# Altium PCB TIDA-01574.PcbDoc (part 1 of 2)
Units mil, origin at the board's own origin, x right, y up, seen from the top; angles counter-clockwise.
Board outline 4950 x 3450 mil, 2 copper layers (Top Layer, Bottom Layer), stack 62 mil thick; 82 components, 33 nets, 179 pads, 119 vias.
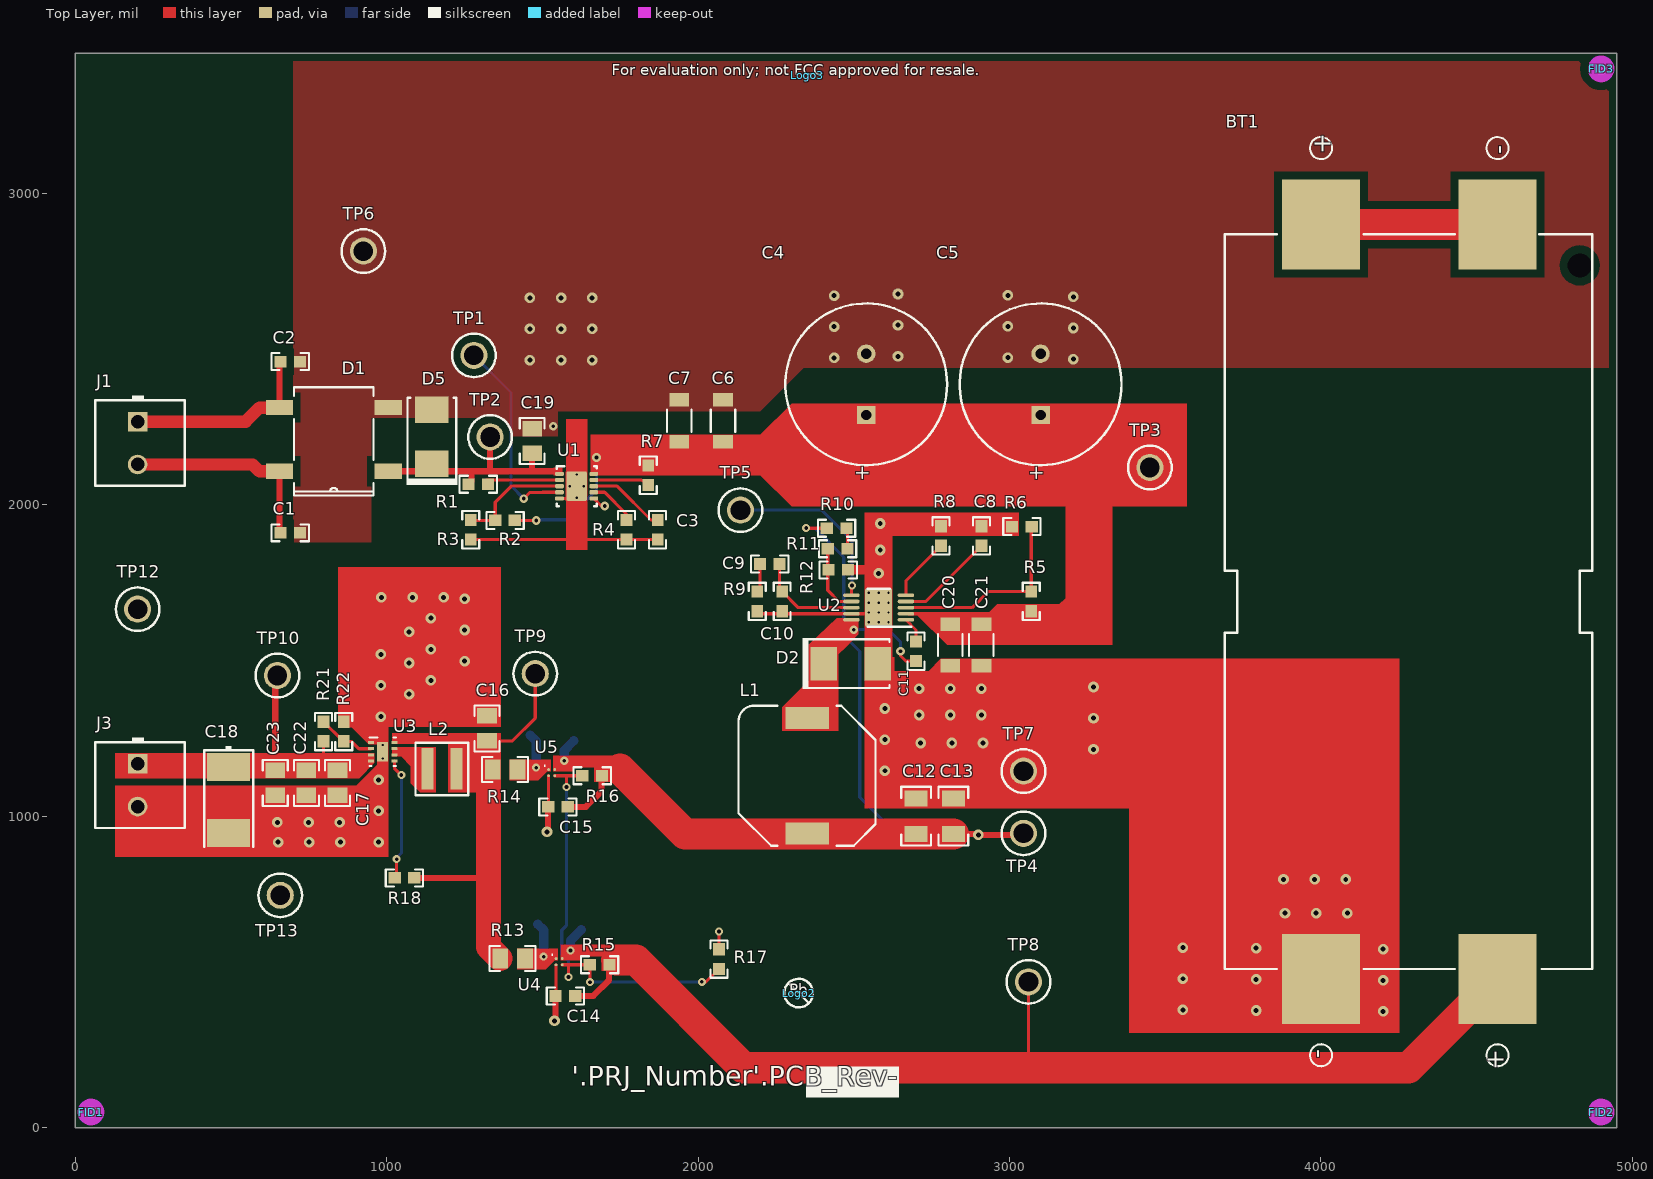
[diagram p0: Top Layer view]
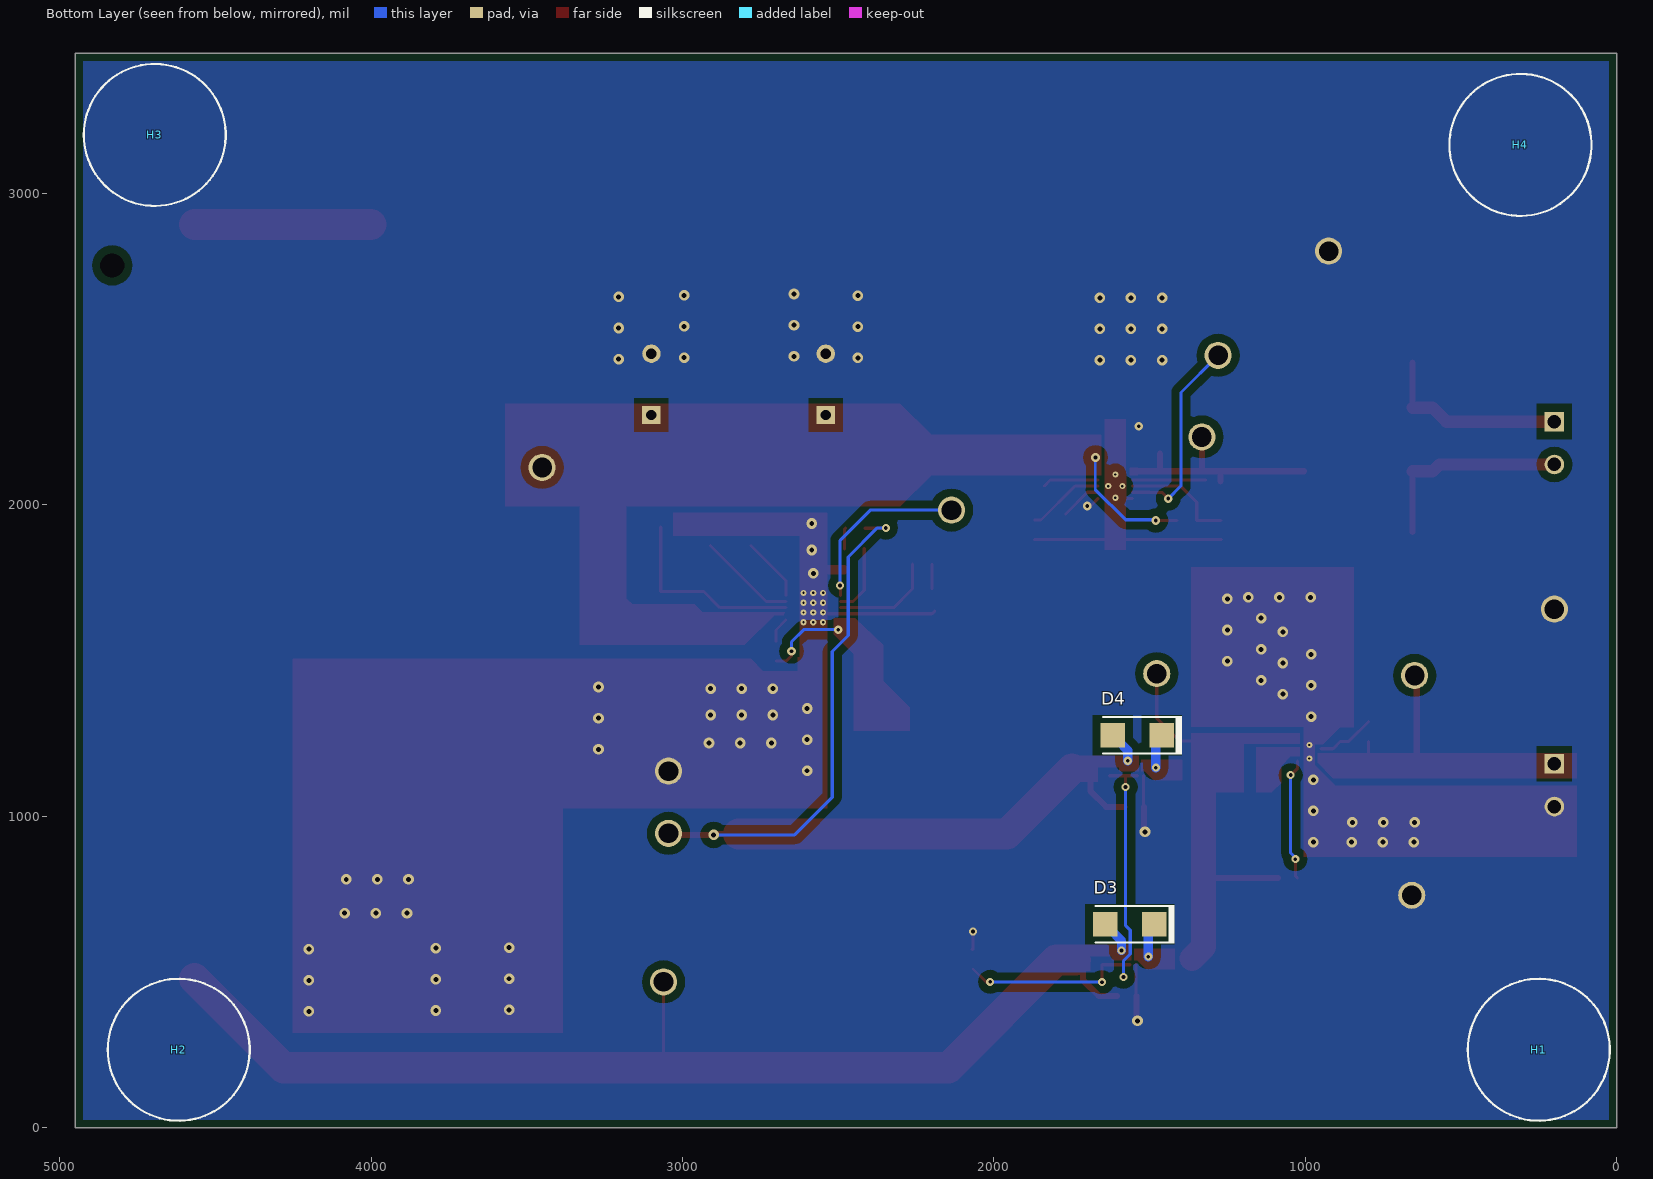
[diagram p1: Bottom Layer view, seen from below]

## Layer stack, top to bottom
Top Solder: solder mask 0.4, Solder Resist, Dk 3.5
Top Layer: signal copper 1.4
Dielectric1: core 59.2, FR-4, Dk 4.8
Bottom Layer: signal copper 1.4
Bottom Solder: solder mask 0.4, Solder Resist, Dk 3.5

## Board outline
0,0 4950,0 4950,3450 0,3450

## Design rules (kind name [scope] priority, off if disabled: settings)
AcuteAngle [All] p1: minimum=4.50000000000000E+0001 checktracksonly=FALSE
AssemblyTestPointUsage [All] p1: valid=2
BoardOutlineClearance BoardOutlineClearance_MountingHoles [OnCopper and InComponentClass('Mounting Holes')] p1: gap=40 ignorepadtopadclearanceinfootprint=FALSE
BoardOutlineClearance BoardOutlineClearance_Poly [OnCopper and IsPoly] p2: gap=25 ignorepadtopadclearanceinfootprint=FALSE
BoardOutlineClearance [OnCopper and Not InComponentClass('Logo') and not InComponentClass('FiducialMark') and not InRegion(1000,500,4000,800) and not InPoly] p3: gap=75 ignorepadtopadclearanceinfootprint=FALSE
Clearance Clearance_Keepouts [((IsTrack Or IsArc) And Not InPoly) And IsFree and IsKeepOut vs ((IsTrack Or IsArc) And Not InPoly) And IsFree and IsKeepOut] p1: gap=0 ignorepadtopadclearanceinfootprint=FALSE
Clearance Clearance_Poly [InPolygon] p2: gap=25 ignorepadtopadclearanceinfootprint=FALSE except(0: Arc-Hole Track-Hole SMDPad-Hole THPad-Hole Via-Hole Fill-Hole Poly-Hole Region-Hole Text-Hole)
Clearance Clearance_FiducialMark [IsKeepOut and InComponentClass('FiducialMark') vs IsPad and InComponentClass('FiducialMark')] p3: gap=0 ignorepadtopadclearanceinfootprint=FALSE
Clearance [All] p4: gap=7.87 ignorepadtopadclearanceinfootprint=FALSE except(0: Arc-Hole Track-Hole SMDPad-Hole THPad-Hole Via-Hole Fill-Hole Poly-Hole Region-Hole Text-Hole)
ComponentClearance ComponentClearance_MountingHoles_FiducialMarks [InComponentClass('Mounting Holes') vs InComponentClass('FiducialMark')] p1: gap=50 collisioncheckmode=3 verticalgap=10 showdistances=FALSE
ComponentClearance ComponentClearance_Shunt [InComponentClass('Header') vs InComponentClass('Shunt')] p2: gap=0 collisioncheckmode=3 verticalgap=0 showdistances=FALSE
ComponentClearance ComponentClearance_Logo [InComponentClass('Logo')] p3: gap=50 collisioncheckmode=3 verticalgap=10 showdistances=FALSE
ComponentClearance ComponentClearance_ScrewToNut [(HasFootprint('NY PMS 440 0025 PH')) vs (HasFootprint('Keystone_1902C'))] p4: gap=5 collisioncheckmode=3 verticalgap=10 showdistances=FALSE
ComponentClearance ComponentClearance_MountingHoles [InComponentClass('Mounting Holes')] p5: gap=250 collisioncheckmode=3 verticalgap=100000 showdistances=FALSE
ComponentClearance ComponentClearance_SmallPassives [HasFootprint('0201*') or HasFootprint('0402*') or HasFootprint('0508') or HasFootprint('0603*') or HasFootprint('0612') or HasFootprint('0805*') or HasFootprint('0815*') or HasFootprint('0830*') or HasFootprint('1206*') or HasFootprint('1210*') or HasFootprint('1808*') or HasFootprint('1812*') or HasFootprint('1825*') or HasFootprint('2010*') or HasFootprint('2220*') or HasFootprint('2225*') or HasFootprint('2512*') or HasFootprint('2728*') or HasFootprint('3518*') vs HasFootprint('0201*') or HasFootprint('0402*') or HasFootprint('0508') or HasFootprint('0603*') or HasFootprint('0612') or HasFootprint('0805*') or HasFootprint('0815*') or HasFootprint('0830*') or HasFootprint('1206*') or HasFootprint('1210*') or HasFootprint('1808*') or HasFootprint('1812*') or HasFootprint('1825*') or HasFootprint('2010*') or HasFootprint('2220*') or HasFootprint('2225*') or HasFootprint('2512*') or HasFootprint('2728*') or HasFootprint('3518*')] p6: gap=14.96 collisioncheckmode=3 verticalgap=10 showdistances=FALSE
ComponentClearance ComponentClearance_THtoSMT [IsThruComponent vs IsSMTComponent] p7: gap=40 collisioncheckmode=3 verticalgap=30 showdistances=FALSE
ComponentClearance ComponentClearance_THtoTH [IsThruComponent vs IsThruComponent] p8: gap=30 collisioncheckmode=3 verticalgap=30 showdistances=FALSE
ComponentClearance [All] p9: gap=30 collisioncheckmode=3 verticalgap=10 showdistances=FALSE
DiffPairsRouting [All] p1: maxlimit=100 minlimit=10 mostfreqgap=10 toplayer_minwidth=15 toplayer_maxwidth=15 toplayer_prefwidth=15 bottomlayer_minwidth=15 bottomlayer_maxwidth=15 bottomlayer_prefwidth=15 maxuncoupledlength=1000
FabricationTestPointUsage TestPointUsage [All] p1: valid=2 allowmultiple=FALSE
FabricationTestpoint Testpoint [All] p1: side=3 testpointundercomponent=TRUE minsize=40 maxsize=100 preferedsize=60 minholesize=0 maxholesize=40 preferedholesize=32 testpointgrid=1 allowsidetop=TRUE allowsidebottom=TRUE usegrid=TRUE gridtolerance=0.01
FanoutControl Fanout_LCC [IsLCC] p1: bgadir=Out bgaviamode=Centered fanoutstyle=Auto fanoutdirection=Alternating viagrid=1 // Fanout_LCC (Default Rule)
FanoutControl Fanout_BGA [IsBGA] p2: bgadir=Out bgaviamode=Centered fanoutstyle=Auto fanoutdirection=Alternating viagrid=1 // Fanout_BGA (Default Rule)
FanoutControl Fanout_Default [All] p4: bgadir=Out bgaviamode=Centered fanoutstyle=Auto fanoutdirection=Alternating viagrid=1 // Fanout_Default (Default Rule)
FanoutControl Fanout_Small [(CompPinCount < 5)] p5: bgadir=Out bgaviamode=Centered fanoutstyle=Auto fanoutdirection=OutThenIn viagrid=1 // Fanout_Small (Default Rule)
Height [All] p1: minheight=0 maxheight=1100 prefheight=500
HoleSize [All] p1: absolutevalues=TRUE maxlimit=251 minlimit=7.87 maxpercent=80.000 minpercent=20.000
MinimumAnnularRing MinimumAnnularRing_ThermalPadVias [IsVia and InAnyComponent] p1: minimumring=5.91
MinimumAnnularRing [All] p2: minimumring=7
MinimumSolderMaskSliver MinimumSolderMaskSliver_Logo [InComponentClass('Logo') vs InComponentClass('Logo')] p1: minsoldermaskwidth=0.7
MinimumSolderMaskSliver [All] p2: minsoldermaskwidth=3.94
PlaneConnect [All] p1: planeconnectstyle=Direct reliefexpansion=10 reliefentries=4 reliefconductorwidth=10 reliefairgap=10
PolygonConnect [All] p1: connectstyle=Direct reliefconductorwidth=10 reliefentries=4 polygonreliefangle="90 Angle" airgapwidth=10
RoutingVias ThermalPadVias [IsVia and InAnyComponent] p1: holewidth=7.87 width=19.68 viastyle="Through Hole" minholewidth=7.87 minwidth=19.68 maxholewidth=12.99 maxwidth=23.62
RoutingVias [All] p2: holewidth=16 width=34 viastyle="Through Hole" minholewidth=7.87 minwidth=26 maxholewidth=40 maxwidth=65
SilkToBoardRegionClearance [Not ((IsComment or IsDesignator) And (Hide <> 'False')) and not InRegion(1000,500,4000,800)] p1:
SilkToSilkClearance SilkToSilkClearance_Pb-FreeLogo [(HasFootprint('Pb-Free_Overlay_Medium') OR HasFootprint('Pb-Free_Overlay_Small')) vs (HasFootprint('Pb-Free_Overlay_Medium') OR HasFootprint('Pb-Free_Overlay_Small'))] p1: silktosilkclearance=0
SilkToSilkClearance [All] p2: silktosilkclearance=4
SilkToSolderMaskClearance SilkToComponentPadClearance [(IsPad or IsFill or IsRegion) and InAnycomponent] p1: minsilkscreentomaskgap=3.5 clearancetoexposedcopper=TRUE
SilkToSolderMaskClearance "Silk to Solder Mask Opening" [All] p2: minsilkscreentomaskgap=4 clearancetoexposedcopper=FALSE
SolderMaskExpansion [All] p1: expansion=1.97
Width [All] p1: maxlimit=100 minlimit=6 preferedwidth=10 checkconnectedcopper=TRUE
14 further rules are at their usual default settings.

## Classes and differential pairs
component class TIDA-01574: BT1 C1 C2 C3 C4 C5 C6 C7 C8 C9 C10 C11 C12 C13 C14 C15 C16 C17 C18 C19 C20 C21 C22 C23 D1 D2 D3 D4 D5 J1 J3 L1 L2 R1 R2 R3 R4 R5 R6 R7 R8 R9 R10 R11 R12 R13 R14 R15 R16 R17 R18 R21 R22 TP1 TP2 TP3 TP4 TP5 TP6 TP7 TP8 TP9 TP10 TP12 TP13 U1 U2 U3 U4 U5
component class FiducialMark: FID1 FID2 FID3
component class AssemblyNote: ZZ2 ZZ3 ZZ4
component class TIDA-01574_Hardware: !PCB FID1 FID2 FID3 H1 H2 H3 H4 Logo2 Logo3 ZZ2 ZZ3 ZZ4

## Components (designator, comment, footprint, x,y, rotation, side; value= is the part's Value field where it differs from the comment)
BT1 "1012" Keystone_1012 4284,1689 r180 top
C1 "C1608X7S2A683K080AB" 0603 690,1910 r0 top value=0.068uF
C2 "C1608X7S2A683K080AB" 0603 690,2460 r0 top value=0.068uF
C3 "C0603C222K5RAC" 0603 1870,1920 r270 top value=2200pF
C4 "EEU-TP1V821B" TP_1250x2500 2540,2387 r90 top value=820uF
C5 "EEU-TP1V821B" TP_1250x2500 3100,2387 r90 top value=820uF
C6 "GRM31CR71H225KA88L" 1206_180 2080,2270 r90 top value=2.2uF
C7 "GRM31CR71H225KA88L" 1206_180 1940,2270 r90 top value=2.2uF
C8 "C0603C103J3GECAUTO" 0603 2910,1900 r90 top value=0.01uF
C9 "GRM188R71E272KA01D" 0603 2230,1810 r180 top value=2700pF
C10 "06035A220JAT2A" 0603 2270,1690 r270 top value=22pF
C11 "C0603C103J3GECAUTO" 0603 2700,1530 r90 top value=0.01uF
C12 "C3216X5R0J226M085AC" 1206 2700,1000 r90 top value=22uF
C13 "C3216X5R0J226M085AC" 1206 2820,1000 r90 top value=22uF
C14 "0603YC104JAT2A" 0603 1573.84,422.84 r180 top value=0.1uF
C15 "0603YC104JAT2A" 0603 1549.84,1029.84 r180 top value=0.1uF
C16 "GRM21BR61A226ME44L" 0805_HV 1322,1282 r90 top value=22uF
C17 "C2012X7R1C225K125AB" 0805_HV 842,1107 r270 top value=2.2uF
C18 "594D476X0016C2T" CC_CASEC 492,1052 r270 top value=47uF
C19 "GRM21BR72A104KAC4L" 0805_HV 1467,2205 r90 top value=0.1uF
C20 "GRM31CR71H225KA88L" 1206_180 2810,1550 r270 top value=2.2uF
C21 "GRM31CR71H225KA88L" 1206_180 2910,1550 r270 top value=2.2uF
C22 "GRM21BR61A226ME44L" 0805_HV 742,1107 r270 top value=22uF
C23 "GRM21BR61A226ME44L" 0805_HV 642,1107 r270 top value=22uF
D1 "DF1502S-T" DF-S 830,2210 r180 top value=200V
D2 "B240-13-F" SMB 2490,1490 r0 top value=40V
D3 "B120-13-F" SMA 1564,653 r0 bottom value=20V
D4 "B120-13-F" SMA 1540,1260 r0 bottom value=20V
D5 "SMBJ33A-13-F" SMB 1145,2219 r90 top value=33V
FID1 "Fiducial" Fiducial10-20 50,50 r0 top
FID2 "Fiducial" Fiducial10-20 4900,50 r0 top
FID3 "Fiducial" Fiducial10-20 4900,3400 r0 top
H1 "SJ-5303 (CLEAR)" Bumpon_SJ5003Transparent 250,250 r180 bottom
H2 "SJ-5303 (CLEAR)" Bumpon_SJ5003Transparent 4618,250 r180 bottom
H3 "SJ-5303 (CLEAR)" Bumpon_SJ5003Transparent 4695,3188 r180 bottom
H4 "SJ-5303 (CLEAR)" Bumpon_SJ5003Transparent 309,3156 r180 bottom
J1 "39357-0002" MOLEX_39357-0002 200,2198.49 r270 top
J3 "39357-0002" MOLEX_39357-0002 200,1100 r270 top
L1 "MSS1048-473MLB" MSS1048 2350,1130 r270 top value=47uH
L2 "XFL4015-471MEC" XFL4015 1177,1152 r180 top value=470nH
Logo2 "Pb-Free Symbol" Pb-Free_Overlay_Small 2323,432 r0 top
Logo3 "FCC disclaimer" FCC_disclaimer 2350,3380 r0 top
R1 "RC0603FR-072ML" 0603 1294,2066 r180 top value=2.00Meg
R2 "CRCW0603866KFKEA" 0603 1380,1950 r0 top value=866k
R3 "CRCW060330K0JNEA" 0603 1270,1920 r90 top value=30k
R4 "RT0603BRD07267KL" 0603 1770,1920 r90 top value=267k
R5 "CRCW06036M65FKEA" 0603 3070,1690 r270 top value=6.65Meg
R6 "RC0603FR-07226KL" 0603 3040,1930 r0 top value=226k
R7 "CRCW0603100KJNEA" 0603 1840,2095 r90 top value=100k
R8 "CRCW0603237KFKEA" 0603 2780,1900 r270 top value=237k
R9 "CRCW060336K5FKEA" 0603 2190,1690 r90 top value=36.5k
R10 "CRCW06031K00FKEA" 0603 2445,1925 r180 top value=1.00k
R11 "CRCW060376K8FKEA" 0603 2448,1859 r0 top value=76.8k
R12 "CRCW060324K9FKEA" 0603 2450,1791 r180 top value=24.9k
R13 "CRCW08050000Z0EA" 0805_HV 1404,543 r180 top value=0
R14 "CRCW08050000Z0EA" 0805_HV 1380,1150 r180 top value=0
R15 "CRCW0603430KJNEA" 0603 1683.84,522.84 r180 top value=430k
R16 "CRCW060312K0JNEA" 0603 1659.84,1129.84 r180 top value=12k
R17 "CRCW060322K0JNEA" 0603 2067,541 r270 top value=22k
R18 "CRCW0603120KJNEA" 0603 1057,802 r180 top value=120k
R21 "CRCW0603316KFKEA" 0603 797,1272 r270 top value=316k
R22 "CRCW0603100KFKEA" 0603 862,1272 r270 top value=100k
TP1 "5008" Keystone5008 1280,2480 r0 top
TP2 "5005" Keystone5005 1332,2218 r0 top
TP3 "5005" Keystone5005 3451,2120 r0 top
TP4 "5005" Keystone5005 3045,945 r0 top
TP5 "5008" Keystone5008 2136,1983 r0 top
TP6 "GND" Keystone5006 925,2815 r0 top
TP7 "GND" Keystone5006 3045,1145 r0 top
TP8 "5005" Keystone5005 3061,468 r0 top
TP9 "5005" Keystone5005 1477,1458 r0 top
TP10 "5005" Keystone5005 649,1452 r0 top
TP12 "GND" Keystone5006 200,1665 r0 top
TP13 "GND" Keystone5006 658,746 r0 top
U1 "TPS26625DRCR" DRC0010J 1610,2060 r0 top
U2 "TPS54040ADGQ" DGQ0010D_N 2580,1670 r180 top
U3 "TPS61021ADSGR" DSG0008A 987,1207 r0 top
U4 "TPS22910AYZVR" YZV0004ADAD 1553.84,532.84 r0 top
U5 "TPS22912CYZVR" YZV0004ADAD 1529.84,1139.84 r0 top
ZZ2 "These assemblies are ESD sensitive, ESD precautions shall be observed." AssemblyNote 185,3829.11 r0 top
ZZ3 "These assemblies must be clean and free from flux and all contaminants. Use of no clean flux is not acceptable." AssemblyNote 185,3740.56 r0 top
ZZ4 "These assemblies must comply with workmanship standards IPC-A-610 Class 2, unless otherwise specified." AssemblyNote 185,3652 r0 top

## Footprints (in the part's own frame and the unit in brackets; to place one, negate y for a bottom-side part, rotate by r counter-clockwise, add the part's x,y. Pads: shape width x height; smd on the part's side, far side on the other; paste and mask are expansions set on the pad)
0603 [mm] "0603 from SM-752 data"
  rect 1x0.95 smd: 1(-0.8,0) 2(0.8,0)
  silkscreen extent -1.52,-0.69 1.52,0.69, body extent -0.87,-0.47 0.87,0.47, height 1
0805_HV [mil] "0805 with 30mil clearance between pads"
  rect 50x63 smd: 1(-40,0) 2(40,0)
  silkscreen extent -74,-40 74,40, body extent -43,-29 43,29, height 57
1206 [mm] "1206 from SM-752 data"
  rect 1.3x1.85 smd: 1(-1.45,0) 2(1.45,0)
  silkscreen extent -2.4,-1.21 2.4,1.21, body extent -1.7,-0.9 1.7,0.9, height 1.35
1206_180 [mm] "1206_180"
  rect 1.1x1.6 smd: 1(-1.7,0) 2(1.7,0)
  silkscreen extent -0.9,-1 0.9,1, body extent -1.75,-0.95 1.75,0.95, height 1.8
AssemblyNote [mil] "Assembly Note"
Bumpon_SJ5003Transparent [mil] "3M Hemispherical Bumpon transparent"
  round 1 on Mech4: 0(0,0)
  silkscreen extent -228,-228 228,228, body extent -219,-219 219,219, height 197
CC_CASEC [mm] "Vishay recommended land pattern"
  rect 2.3x3.5 smd: 1(-2.7,0) 2(2.7,0)
  silkscreen extent -4.4,-2 3.81,2, body extent -4.1,-1.75 3,1.75, height 2.8
DF-S [mil] "Diodes Inc. recommended land pattern per ap02001.pdf rev 30"
  rect 88x49 smd: 1(-174.5,102.36) 2(-174.5,-102.36) 3(174.5,-102.36) 4(174.5,102.36)
  silkscreen extent -128,-168 128,180, body extent -205,-168 205,168, height 108
DGQ0010D_N [mm] "TSSOP, 10-Leads, Body 3x3mm, Pitch 0.5mm, Thermal Pad 1.88x1.57mm, IPC Medium Density"
  rrect100% 1.35x0.3 smd: 1(-2.225,1) 2(-2.225,0.5) 3(-2.225,0) 4(-2.225,-0.5) 5(-2.225,-1) 6(2.225,-1) 7(2.225,-0.5) 8(2.225,0) 9(2.225,0.5) 10(2.225,1)
  rrect9% 2.2x3.1 smd paste-2 mask-2: 11(0,0)
  rrect5% 1.83x1.89 on Top Paste: 11(0,0)
  rrect5% 1.83x1.89 on Top Solder: 11(0,0)
  silkscreen extent -2.65,-1.55 0.9,1.55, body extent -2.46,-1.5 2.46,1.5, height 1.1
DRC0010J [mm] "SON, 10-Leads, Body 3x3mm, Pitch 0.5mm, Thermal Pad 2.4x1.65mm, TI Recommended"
  rrect57% 0.7x0.35 smd paste-0.05 mask-0.05: 1(-1.4,1) 2(-1.4,0.5) 3(-1.4,0) 4(-1.4,-0.5) 5(-1.4,-1) 6(1.4,-1) 7(1.4,-0.5) 8(1.4,0) 9(1.4,0.5) 10(1.4,1)
  rrect40% 0.25x0.34 on Top Paste: 11(-0.25,-1.53) 11(-0.25,1.53) 11(0.25,-1.53) 11(0.25,1.53)
  rrect9% 1.5x1.06 on Top Paste: 11(0,-0.63) 11(0,0.63)
  rrect12% 1.65x2.4 smd paste-1 mask-2: 11(0,0)
  Top Layer region: -0.25,1.1 0.25,1.1 0.25,1.75 -0.25,1.75
  Top Layer region: -0.25,-1.75 0.25,-1.75 0.25,-1.1 -0.25,-1.1
  Top Layer region: -0.775,-1.25 -0.425,-1.25 -0.425,-1.65 -0.417,-1.688 -0.396,-1.721 -0.363,-1.742 -0.325,-1.75 -0.325,-1.75 -0.325,-1.75 -0.175,-1.75 -0.175,-1.75 -0.137,-1.742 -0.104,-1.721 -0.083,-1.688 -0.075,-1.65 -0.075,-1.65 -0.075,-1.25 0.075,-1.25 0.075,-1.65 0.083,-1.688 0.104,-1.721 0.137,-1.742 0.175,-1.75 0.175,-1.75 0.175,-1.75 0.325,-1.75 0.325,-1.75 0.363,-1.742 0.396,-1.721 0.417,-1.688 0.425,-1.65 0.425,-1.65 0.425,-1.25 0.775,-1.25 0.813,-1.242 0.846,-1.221 0.867,-1.188 0.875,-1.15 0.875,-1.15 0.875,1.15 0.867,1.188 0.846,1.221 0.813,1.242 0.775,1.25 0.775,1.25 0.425,1.25 0.425,1.65 0.417,1.688 0.396,1.721 0.363,1.742 0.325,1.75 0.325,1.75 0.175,1.75 0.137,1.742 0.104,1.721 0.083,1.688 0.075,1.65 0.075,1.65 0.075,1.25 -0.075,1.25 -0.075,1.65 -0.083,1.688 -0.104,1.721 -0.137,1.742 -0.175,1.75 -0.175,1.75 -0.325,1.75 -0.363,1.742 -0.396,1.721 -0.417,1.688 -0.425,1.65 -0.425,1.65 -0.425,1.25 -0.775,1.25 -0.813,1.242 -0.846,1.221 -0.867,1.188 -0.875,1.15 -0.875,1.15 -0.875,-1.15 -0.867,-1.188 -0.846,-1.221 -0.813,-1.242 -0.775,-1.25
  silkscreen extent -1.63,-1.63 1.63,1.63, body extent -1.5,-1.5 1.5,1.5, height 0.77
DSG0008A [mm] "SON, 8-Leads, Body 2x2mm, Pitch 0.5mm, Thermal Pad 1.6x0.9mm, TI Recommended"
  rrect40% 0.5x0.25 smd: 1(-0.95,0.75) 2(-0.95,0.25) 3(-0.95,-0.25) 4(-0.95,-0.75) 5(0.95,-0.75) 6(0.95,-0.25) 7(0.95,0.25) 8(0.95,0.75)
  rrect14% 0.9x0.7 on Top Paste: 9(0,-0.45) 9(0,0.45)
  rrect11% 0.9x1.6 smd paste-0.45: 9(0,0)
  silkscreen extent -1.07,-1.15 1.07,1.15, body extent -1,-1 1,1, height 0.77
FCC_disclaimer [mil]
Fiducial10-20 [mm]
  round 1 smd mask+0.5: 1(0,0)
  Top Layer keep-out circle w1.178: c0,0 r0.5
Keystone5005 [mil] "Keystone Compact loops"
  round 87 hole 63: 1(0,0)
  silkscreen extent -70,-70 70,70, body extent -63,-63 62,63, height 225
Keystone5006 [mil] "Keystone Compact loops"
  round 87 hole 63: 1(0,0)
  silkscreen extent -70,-70 70,70, body extent -63,-63 62,63, height 225
Keystone5008 [mil] "Keystone Compact loops"
  round 87 hole 63: 1(0,0)
  silkscreen extent -70,-70 70,70, body extent -63,-63 62,63, height 225
Keystone_1012 [mm] "Battery holder for 2AA, SMD"
  rect 6.35x7.34 smd: 1(-7.21,30.76) 2(-7.21,-30.76) 3(7.21,30.76) 4(7.21,-30.76)
  round 0 hole 1.98 unplated: MH1(-13.9,-27.425)
  silkscreen extent -14.92,-37.9 15.06,37.9, body extent -14.92,-34.56 15.06,34.56, height 14.86
MOLEX_39357-0002 [mm] "Terminal Block, 3.5 mm, 2x1, TH"
  rect 1.6x1.6 hole 1.1: 1(-1.75,0)
  round 1.6 hole 1.1: 2(1.75,0)
  silkscreen extent -3.86,-3.45 3.5,3.84, body extent -3.55,-3.45 3.56,3.84, height 8.51
MSS1048 [mm] "Coilcraft recommended land pattern Document 462-2 Revised 06/09/09"
  rect 1.78x3.56 smd: 1(-4.7,0) 2(4.7,0)
  silkscreen extent -5.72,-5.59 5.72,5.59, body extent -5.15,-5.1 5.15,5.1, height 5.12
Pb-Free_Overlay_Small [mil]
  silkscreen extent -46,-46 46,46
SMA [mm] "Molded Diode, 2-Leads, Body 4.3x2.6mm, IPC Medium Density, based on OnSemi component dimensions and land pattern"
  rect 2x2 smd: 1(-2,0) 2(2,0)
  silkscreen extent -3.66,-1.57 2.79,1.57, body extent -2.6,-1.3 2.6,1.3, height 2.42
SMB [mil] "Molded Diode, 2-Leads, Body 5.4x3.6mm, IPC Medium Density, based on OnSemi component dimensions"
  rect 85x107.99 smd: 1(-87.01,0) 2(87.01,0)
  silkscreen extent -155,-82 125,82, body extent -106,-71 106,71, height 91
TP_1250x2500 [mm] "PANASONIC"
  rect 1.5x1.5 hole 0.85: 1(-2.5,0)
  round 1.5 hole 0.85: 2(2.5,0)
  silkscreen extent -6.6,-6.6 6.6,6.6, body extent -6.5,-6.5 6.51,6.5, height 27.01
XFL4015 [mm] "SMD, 2-Leads, Body 4x4mm"
  rect 0.98x3.4 smd: 1(-1.185,0) 2(1.185,0)
  silkscreen extent -2.15,-2.15 2.15,2.15, body extent -2.15,-2.15 2.15,2.15, height 1.6
YZV0004ADAD [mm] "BGA, 4-Leads, Pitch 0.5mm"
  round 0.23 smd mask+0.04: A1(-0.25,0.25) A2(0.25,0.25) B1(-0.25,-0.25) B2(0.25,-0.25)
  silkscreen extent -0.63,0.51 -0.53,0.61, body extent -0.46,-0.46 0.46,0.46, height 0.56

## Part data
BT1: library part CMP-0003769-1, "Battery holder for 2AA, SMD", Manufacturer=Keystone, Supplier Part Number 1=36-1012-ND
C1 C2: library part CMP-0007061-4, "CAP, CERM, 0.068 uF, 100 V, +/- 10%, X7S, 0603", Cap_Case=0603, Manufacturer=TDK, Supplier Part Number 1=445-6034-1-ND, TempCo=X7S, Tolerance_%=10%, Value1="0.074084 ohm", Value2=100V, ValueDisplayed=0.068uF
C3: library part CMP-0006897-4, "CAP, CERM, 2200 pF, 50 V, +/- 10%, X7R, 0603", Cap_Case=0603, Manufacturer=Kemet, Supplier Part Number 1=1362428, TempCo=X7R, Tolerance_%=10%, Value1=Unknown, Value2=50V, ValueDisplayed=2200pF
C4 C5: library part CMP-0010356-2, "CAP, AL, 820 uF, 35 V, +/- 20%, 0.03 ohm, AEC-Q200 Grade 1, TH", Cap_Case=12.5x25mm, Manufacturer=Panasonic, Supplier Part Number 1=P15712CT-ND, Tolerance_%=20%, Value1="0.03 ohm", Value2=35V, ValueDisplayed=820uF
C6 C7 C20 C21: library part CMP-0008968-2, "CAP, CERM, 2.2 uF, 50 V, +/- 10%, X7R, 1206", Cap_Case=1206, Manufacturer=MuRata, Supplier Part Number 1=490-3367-1-ND, TempCo=X7R, Tolerance_%=10%, Value1=Unknown, Value2=50V, ValueDisplayed=2.2uF
C8 C11: library part CMP-0006849-4, "CAP, CERM, 0.01 uF, 25 V, +/- 5%, C0G/NP0, AEC-Q200 Grade 1, 0603", Cap_Case=0603, Manufacturer=Kemet, Supplier Part Number 1=399-14102-1-ND, TempCo=C0G/NP0, Tolerance_%=5%, Value1=Unknown, Value2=25V, ValueDisplayed=0.01uF
C9: library part CMP-0007416-5, "CAP, CERM, 2700 pF, 25 V, +/- 10%, X7R, 0603", Cap_Case=0603, Manufacturer=MuRata, Supplier Part Number 1=GRM188R71E272KA01D-ND, TempCo=X7R, Tolerance_%=10%, Value1=Unknown, Value2=25V, ValueDisplayed=2700pF
C10: library part CMP-0006775-4, "CAP, CERM, 22 pF, 50 V, +/- 5%, C0G/NP0, 0603", Cap_Case=0603, Manufacturer=AVX, Supplier Part Number 1=478-1167-1-ND, TempCo=C0G/NP0, Tolerance_%=5%, Value1="0.259 ohm", Value2=50V, ValueDisplayed=22pF
C12 C13: library part CMP-0008648-2, "CAP, CERM, 22 uF, 6.3 V, +/- 20%, X5R, 1206", Cap_Case=1206, Manufacturer=TDK, Supplier Part Number 1=445-7717-1-ND, TempCo=X5R, Tolerance_%=20%, Value1="0.002 ohm", Value2=6.3V, ValueDisplayed=22uF
C14 C15: library part CMP-0006808-4, "CAP, CERM, 0.1 uF, 16 V, +/- 5%, X7R, 0603", Cap_Case=0603, Manufacturer=AVX, Supplier Part Number 1=478-3726-1-ND, TempCo=X7R, Tolerance_%=5%, Value1="0.039 ohm", Value2=16V, ValueDisplayed=0.1uF
C16 C22 C23: library part CMP-0008286-2, "CAP, CERM, 22 uF, 10 V, +/- 20%, X5R, 0805", Cap_Case=0805, Manufacturer=MuRata, Supplier Part Number 1=490-10746-1-ND, TempCo=X5R, Tolerance_%=20%, Value1=Unknown, Value2=10V, ValueDisplayed=22uF
C17: library part CMP-0007867-2, "CAP, CERM, 2.2 uF, 16 V, +/- 10%, X7R, 0805", Cap_Case=0805, Manufacturer=TDK, Supplier Part Number 1=445-1420-1-ND, TempCo=X7R, Tolerance_%=10%, Value1="0.0049 ohm", Value2=16V, ValueDisplayed=2.2uF
C18: library part CMP-0012004-2, "CAP, TA, 47 uF, 16 V, +/- 20%, 0.11 ohm, SMD", Cap_Case=C, Manufacturer=Vishay-Sprague, Supplier Part Number 1=718-1002-1-ND, Tolerance_%=20%, Value1="0.11 ohm", Value2=16V, ValueDisplayed=47uF
C19: library part CMP-0008363-2, "CAP, CERM, 0.1 uF, 100 V, +/- 10%, X7R, 0805", Cap_Case=0805, Manufacturer=MuRata, Supplier Part Number 1=490-12005-1-ND, TempCo=X7R, Tolerance_%=10%, Value1=Unknown, Value2=100V, ValueDisplayed=0.1uF
D1: library part CMP-0029207-2, "Diode, Switching-Bridge, 200 V, 1.5 A, DF-S", Manufacturer="Diodes Inc.", Supplier Part Number 1=DF1502SDICT-ND, Value1=1.5A, Value2=1.1V
D2: library part CMP-0028402-1, "Diode, Schottky, 40 V, 2 A, SMB", Manufacturer="Diodes Inc.", Supplier Part Number 1=B240-FDICT-ND, Value1=2A, Value2=0.5V
D3 D4: library part CMP-0028374-1, "Diode, Schottky, 20 V, 1 A, SMA", Manufacturer="Diodes Inc.", Supplier Part Number 1=B120-FDICT-ND, Value1=1A, Value2=0.5V
D5: library part CMP-0005563-2, "Diode, TVS, Uni, 33 V, 53.3 Vc, SMB", Manufacturer="Diodes Inc.", Power_W=5W, Supplier Part Number 1=SMBJ33A-FDICT-ND
FID1 FID2 FID3: library part CMP-0077181-1, "Fiducial mark.  There is nothing to buy or mount.", Manufacturer=N/A
H1 H2 H3 H4: library part CMP-0003620-1, "Bumpon, Hemisphere, 0.44 X 0.20, Clear", Manufacturer=3M, Supplier Part Number 1=SJ5303-7-ND
J1 J3: library part CMP-0055341-1, "Terminal Block, 3.5 mm, 2x1, Tin, TH", Manufacturer=Molex, Supplier Part Number 1=WM7877-ND
L1: library part CMP-0061449-2, "Inductor, Shielded Drum Core, Ferrite, 47 uH, 2.2 A, 0.13 ohm, SMD", Manufacturer=Coilcraft, Value1="0.13 ohm", Value2=2.2A, ValueDisplayed=47uH
L2: library part CMP-0061147-1, "Inductor, Shielded, Composite, 470 nH, 3.5 A, 0.0076 ohm, SMD", Manufacturer=Coilcraft, Supplier Part Number 1=994-XFL4015-471MEC, Value1="0.0076 ohm", Value2=3.5A, ValueDisplayed=470nH
Logo2: library part CMP-0074839-1
Logo3: library part CMP-0074847-1, "FCC_disclaimer"
R1: library part CMP-0023004-2, "RES, 2.00 M, 1%, 0.1 W, 0603", Manufacturer="Yageo America", Power_W=100mW, Supplier Part Number 1=311-2.00MHRCT-ND, TempCo="200 ppm/C", Tolerance_%=1%, Value2=0.1W, Value_Code=2M00, ValueDisplayed=2.00M
R2: library part CMP-0022626-2, "RES, 866 k, 1%, 0.1 W, 0603", Manufacturer=Vishay-Dale, Power_W=100mW, Supplier Part Number 1=541-866KHCT-ND, TempCo="100 ppm/C", Tolerance_%=1%, Value2=0.1W, Value_Code=866k
R3: library part CMP-0025782-3, "RES, 30 k, 5%, 0.1 W, 0603", Manufacturer=Vishay-Dale, Power_W=100mW, Supplier Part Number 1=541-30KGCT-ND, TempCo="200 ppm/C", Tolerance_%=5%, Value2=0.1W, Value_Code=30k0, ValueDisplayed=30k
R4: library part CMP-0024012-3, "RES, 267 k, 0.1%, 0.1 W, 0603", Manufacturer="Yageo America", Power_W=100mW, TempCo="25 ppm/C", Tolerance_%=0.1%, Value2=0.1W, Value_Code=267k
R5: library part CMP-0022569-4, "RES, 6.65 M, 1%, 0.1 W, AEC-Q200 Grade 0, 0603", Manufacturer=Vishay-Dale, Power_W=100mW, Supplier Part Number 1=541-6.65MHCT-ND, TempCo="100 ppm/C", Tolerance_%=1%, Value2=0.1W, Value_Code=6M65, ValueDisplayed=6.65M
R6: library part CMP-0022921-2, "RES, 226 k, 1%, 0.1 W, 0603", Manufacturer="Yageo America", Power_W=100mW, Supplier Part Number 1=311-226KHRCT-ND, TempCo="200 ppm/C", Tolerance_%=1%, Value2=0.1W, Value_Code=226k
R7: library part CMP-0025698-3, "RES, 100 k, 5%, 0.1 W, 0603", Manufacturer=Vishay-Dale, Power_W=100mW, Supplier Part Number 1=541-100KGCT-ND, TempCo="200 ppm/C", Tolerance_%=5%, Value2=0.1W, Value_Code=100k
R8: library part CMP-0022226-3, "RES, 237 k, 1%, 0.1 W, 0603", Manufacturer=Vishay-Dale, Power_W=100mW, Supplier Part Number 1=541-237KHCT-ND, TempCo="100 ppm/C", Tolerance_%=1%, Value2=0.1W, Value_Code=237k
R9: library part CMP-0022356-3, "RES, 36.5 k, 1%, 0.1 W, 0603", Manufacturer=Vishay-Dale, Power_W=100mW, Supplier Part Number 1=541-36.5KHCT-ND, TempCo="100 ppm/C", Tolerance_%=1%, Value2=0.1W, Value_Code=36k5, ValueDisplayed=36.5k
R10: library part CMP-0022109-4, "RES, 1.00 k, 1%, 0.1 W, 0603", Manufacturer=Vishay-Dale, Power_W=100mW, Supplier Part Number 1=541-1.00KHCT-ND, TempCo="100 ppm/C", Tolerance_%=1%, Value2=0.1W, Value_Code=1k00, ValueDisplayed=1.00k
R11: library part CMP-0022593-3, "RES, 76.8 k, 1%, 0.1 W, 0603", Manufacturer=Vishay-Dale, Power_W=100mW, Supplier Part Number 1=541-76.8KHCT-ND, TempCo="100 ppm/C", Tolerance_%=1%, Value2=0.1W, Value_Code=76k8, ValueDisplayed=76.8k
R12: library part CMP-0022237-3, "RES, 24.9 k, 1%, 0.1 W, 0603", Manufacturer=Vishay-Dale, Power_W=100mW, Supplier Part Number 1=541-24.9KHCT-ND, TempCo="100 ppm/C", Tolerance_%=1%, Value2=0.1W, Value_Code=24k9, ValueDisplayed=24.9k
R13 R14: library part CMP-0020442-2, "RES, 0, 5%, 0.125 W, 0805", Manufacturer=Vishay-Dale, Power_W=125mW, Supplier Part Number 1=541-0.0ACT-ND, TempCo="200 ppm/C", Tolerance_%=5%, Value2=0.125W, Value_Code=0000, ValueDisplayed=0
R15: library part CMP-0025808-3, "RES, 430 k, 5%, 0.1 W, 0603", Manufacturer=Vishay-Dale, Power_W=100mW, Supplier Part Number 1=541-430KGCT-ND, TempCo="200 ppm/C", Tolerance_%=5%, Value2=0.1W, Value_Code=430k
R16: library part CMP-0025711-3, "RES, 12 k, 5%, 0.1 W, 0603", Manufacturer=Vishay-Dale, Power_W=100mW, Supplier Part Number 1=541-12KGCT-ND, TempCo="200 ppm/C", Tolerance_%=5%, Value2=0.1W, Value_Code=12k0, ValueDisplayed=12k
R17: library part CMP-0025757-3, "RES, 22 k, 5%, 0.1 W, 0603", Manufacturer=Vishay-Dale, Power_W=100mW, Supplier Part Number 1=541-22KGCT-ND, TempCo="200 ppm/C", Tolerance_%=5%, Value2=0.1W, Value_Code=22k0, ValueDisplayed=22k
R18: library part CMP-0025709-3, "RES, 120 k, 5%, 0.1 W, 0603", Manufacturer=Vishay-Dale, Power_W=100mW, Supplier Part Number 1=541-120KGCT-ND, TempCo="200 ppm/C", Tolerance_%=5%, Value2=0.1W, Value_Code=120k
R21: library part CMP-0022328-3, "RES, 316 k, 1%, 0.1 W, 0603", Manufacturer=Vishay-Dale, Power_W=100mW, Supplier Part Number 1=541-316KHCT-ND, TempCo="100 ppm/C", Tolerance_%=1%, Value2=0.1W, Value_Code=316k
R22: library part CMP-0021990-3, "RES, 100 k, 1%, 0.1 W, 0603", Manufacturer=Vishay-Dale, Power_W=100mW, Supplier Part Number 1=541-100KHCT-ND, TempCo="100 ppm/C", Tolerance_%=1%, Value2=0.1W, Value_Code=100k
TP1 TP5: library part CMP-0055145-1, "Test Point, Compact, Orange, TH", Color=Orange, Manufacturer=Keystone, Supplier Part Number 1=36-5008-ND
TP2 TP3 TP4 TP8 TP9 TP10: library part CMP-0055142-1, "Test Point, Compact, Red, TH", Color=Red, Manufacturer=Keystone, Supplier Part Number 1=36-5005-ND
TP6 TP7 TP12 TP13: library part CMP-0055143-1, "Test Point, Compact, Black, TH", Color=Black, Manufacturer=Keystone, PartNumber=5006, Supplier Part Number 1=36-5006-ND
U1: library part CMP-0013395-4, "7V - 57V, 800mA Industrial eFuse with Integrated Reverse Polarity Protection, DRC0010J (VSON-10)", Alternate Manufacturer="Texas Instruments", Alternate PartNumber=TPS26625DRCT
U2: library part CMP-0067022-2, "3.5V to 42V Input, 0.5A Step-Down Converter with Eco-Mode, DGQ0010D (VSSOP-10)", Alternate Manufacturer="Texas Instruments"
U3: library part CMP-0074064-2, "3-A Boost Converter with 0.5-V Ultra Low Input Voltage, DSG0008A (WSON-8)", Alternate Manufacturer="Texas Instruments", Alternate PartNumber=TPS61021ADSGT
U4: library part CMP-0066643-1, "5.5V, 2A, 61mO Active-Low Load Switch With Reverse Current Protection, YZV0004ADAD (DSBGA-4)", Alternate Manufacturer="Texas Instruments", Alternate PartNumber=TPS22910AYZVT
U5: library part CMP-0066644-1, "5.5V, 2A, 61mO Load Switch With Reverse Current Protection, YZV0004ADAD (DSBGA-4)", Alternate Manufacturer="Texas Instruments", Alternate PartNumber=TPS22912CYZVT
ZZ2: library part CMP-0077236-1
ZZ3: library part CMP-0077237-1
ZZ4: library part CMP-0077238-1

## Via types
v1: diameter 34, hole 16, Top Layer to Bottom Layer, 81 vias
v2: diameter 26, hole 12, Top Layer to Bottom Layer, 13 vias
v3: diameter 19.68, hole 7.87, Top Layer to Bottom Layer, 12 vias
v4: diameter 28, hole 12, Top Layer to Bottom Layer, 7 vias
v5: diameter 19.68, hole 7.87, Top Layer to Bottom Layer, tented both sides, 6 vias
